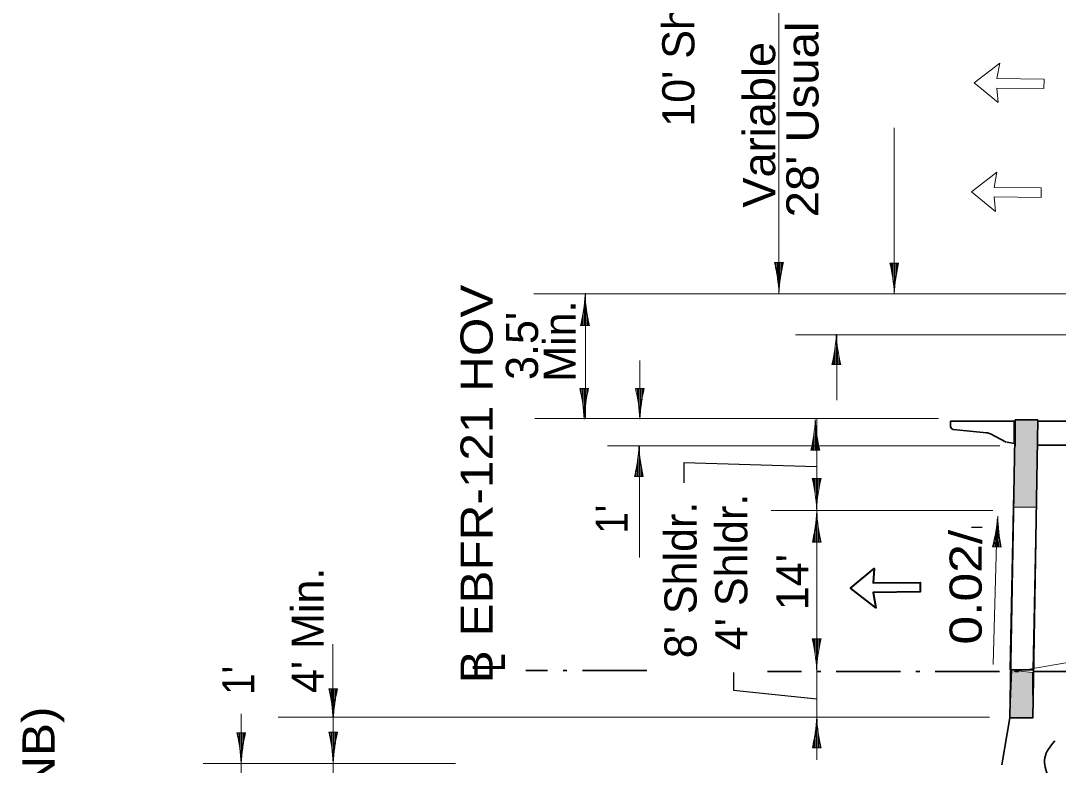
# Model space of a CAD drawing. Extents: x 2363427 to 2368559, y 6957299 to 6980140.
# Drawn here: x 2364021.2 to 2364472.9, y 6965478.2 to 6965802.2 of the extents above; entities that cross this region are included whole.
import ezdxf
from ezdxf.enums import TextEntityAlignment as Align

# ---------------------------------------------------------------- set-up
doc = ezdxf.new("R2010")
doc.units = 0
doc.header["$LTSCALE"] = 5.6
doc.linetypes.add('DOT_DASHED', pattern=[7.7, 5, -1.2, 0.3, -1.2])
for name, color, linetype, lineweight in [('3', 7, 'Continuous', 35), ('4', 7, 'Continuous', 13), ('40', 7, 'Continuous', 35), ('8', 7, 'Continuous', 13)]:
    doc.layers.add(name, color=color, linetype=linetype, lineweight=lineweight)

msp = doc.modelspace()

# ---------------------------------------------------------------- hatches: boundary and pattern name
at = {"layer": '3'}
for points in [[(2364453.307, 6965590.426), (2364463.308, 6965590.426), (2364464.111, 6965628.54), (2364454.108, 6965628.448)], [(2364451.842, 6965498.794), (2364461.842, 6965498.706), (2364461.692, 6965518.588), (2364452.71, 6965519.586)]]:
    msp.add_hatch(color=256, dxfattribs=at).paths.add_polyline_path(points)

# ---------------------------------------------------------------- linework, layer by layer
for p, q in [((2364426.073, 6965627.886), (2364426.073, 6965625.572)), ((2364454.108, 6965628.448), (2364451.842, 6965498.794)), ((2364454.108, 6965628.448), (2364464.111, 6965628.54)), ((2364454.108, 6965628.448), (2364454.108, 6965622.824)), ((2364464.108, 6965628.406), (2364461.842, 6965498.706)), ((2364464.128, 6965627.874), (2364534.151, 6965627.874)), ((2364427.179, 6965624.35), (2364441.663, 6965622.896)), ((2364454.108, 6965617.198), (2364454.108, 6965622.824)), ((2364443.493, 6965622.354), (2364450.328, 6965618.84)), ((2364450.496, 6965618.774), (2364450.506, 6965618.748)), ((2364463.949, 6965617.418), (2364530.245, 6965617.418)), ((2364461.843, 6965519.618), (2364451.842, 6965519.618)), ((2364451.842, 6965498.794), (2364448.359, 6965478.362)), ((2364461.843, 6965498.794), (2364451.842, 6965498.794))]:
    msp.add_line(p, q, dxfattribs=at)
at = {"layer": '3', "lineweight": 13}
msp.add_line((2364576.328, 6965540.2), (2364453.55, 6965518.805), dxfattribs=at)
at = {"layer": '3', "linetype": 'DOT_DASHED'}
msp.add_line((2364293.747, 6965519.428), (2364241.191, 6965519.428), dxfattribs=at)
at = {"layer": '3'}
for points in [[(2364453.793, 6965618.256), (2364453.793, 6965627.886), (2364426.073, 6965627.886)], [(2364450.707, 6965618.718), (2364453.847, 6965618.248), (2364450.506, 6965618.748)]]:
    msp.add_lwpolyline(points, dxfattribs=at)
at = {"layer": '3', "lineweight": 13}
for points in [[(2364453.307, 6965590.426), (2364463.308, 6965590.426), (2364464.111, 6965628.54), (2364454.108, 6965628.448)], [(2364451.842, 6965519.618), (2364461.843, 6965519.618), (2364463.308, 6965590.426), (2364453.307, 6965590.426)], [(2364451.842, 6965498.794), (2364461.842, 6965498.706), (2364461.692, 6965518.588), (2364452.71, 6965519.586)]]:
    msp.add_lwpolyline(points, close=True, dxfattribs=at)
at = {"layer": '3'}
for centre, radius, start, end in [((2364427.303, 6965625.572), 1.229, 180, 264.27822), ((2364441.152, 6965617.803), 5.12, 62.77128, 84.26462)]:
    msp.add_arc(centre, radius, start, end, dxfattribs=at)
msp.add_spline([(2364469.292, 6965454.722), (2364470.404, 6965467.69), (2364468.551, 6965473.248), (2364467.068, 6965481.398), (2364471.517, 6965488.808)], degree=3, dxfattribs=at)
at = {"layer": '4'}
for p, q in [((2364351.339, 6965683.61), (2364351.339, 6965915.843)), ((2364401.539, 6965683.37), (2364401.539, 6965755.631)), ((2364353.253, 6965696.922), (2364349.423, 6965696.922)), ((2364353.253, 6965696.922), (2364349.423, 6965696.922)), ((2364349.903, 6965696.922), (2364349.903, 6965694.54)), ((2364349.903, 6965696.922), (2364349.903, 6965694.54)), ((2364350.403, 6965696.922), (2364350.403, 6965692.06)), ((2364350.403, 6965696.922), (2364350.403, 6965692.06)), ((2364350.903, 6965696.922), (2364350.903, 6965688.312)), ((2364350.903, 6965696.922), (2364350.903, 6965688.312)), ((2364351.403, 6965696.922), (2364351.403, 6965684.358)), ((2364351.403, 6965696.922), (2364351.403, 6965684.358)), ((2364351.903, 6965696.922), (2364351.903, 6965689.572)), ((2364351.903, 6965696.922), (2364351.903, 6965689.572)), ((2364352.403, 6965696.922), (2364352.403, 6965692.645)), ((2364352.403, 6965696.922), (2364352.403, 6965692.645)), ((2364352.903, 6965696.922), (2364352.903, 6965695.336)), ((2364352.903, 6965696.922), (2364352.903, 6965695.336)), ((2364399.625, 6965696.681), (2364403.455, 6965696.681)), ((2364399.625, 6965696.681), (2364403.455, 6965696.681)), ((2364399.975, 6965696.681), (2364399.975, 6965695.097)), ((2364399.975, 6965696.681), (2364399.975, 6965695.097)), ((2364400.475, 6965696.681), (2364400.475, 6965692.405)), ((2364400.475, 6965696.681), (2364400.475, 6965692.405)), ((2364400.975, 6965696.681), (2364400.975, 6965689.331)), ((2364400.975, 6965696.681), (2364400.975, 6965689.331)), ((2364401.475, 6965696.681), (2364401.475, 6965684.117)), ((2364401.475, 6965696.681), (2364401.475, 6965684.117)), ((2364401.975, 6965696.681), (2364401.975, 6965688.072)), ((2364401.975, 6965696.681), (2364401.975, 6965688.072)), ((2364402.475, 6965696.681), (2364402.475, 6965691.819)), ((2364402.475, 6965696.681), (2364402.475, 6965691.819)), ((2364402.975, 6965696.681), (2364402.975, 6965694.3)), ((2364402.975, 6965696.681), (2364402.975, 6965694.3)), ((2364489.927, 6965683.37), (2364244.68, 6965683.37)), ((2364266.973, 6965669.578), (2364266.973, 6965682.142)), ((2364267.09, 6965683.62), (2364267.09, 6965629.024)), ((2364266.473, 6965669.578), (2364266.473, 6965678.188)), ((2364267.473, 6965669.578), (2364267.473, 6965676.928)), ((2364265.973, 6965669.578), (2364265.973, 6965674.44)), ((2364267.973, 6965669.578), (2364267.973, 6965673.854)), ((2364268.823, 6965669.578), (2364264.993, 6965669.578)), ((2364265.473, 6965669.578), (2364265.473, 6965671.96)), ((2364268.473, 6965669.578), (2364268.473, 6965671.162)), ((2364483.333, 6965665.466), (2364358.604, 6965665.466)), ((2364376.368, 6965652.54), (2364376.368, 6965665.104)), ((2364376.485, 6965637.068), (2364376.485, 6965665.46)), ((2364375.868, 6965652.54), (2364375.868, 6965661.15)), ((2364376.868, 6965652.54), (2364376.868, 6965659.89)), ((2364290.781, 6965630.29), (2364290.781, 6965654.358)), ((2364374.868, 6965652.54), (2364374.868, 6965654.922)), ((2364375.368, 6965652.54), (2364375.368, 6965657.402)), ((2364377.368, 6965652.54), (2364377.368, 6965656.816)), ((2364378.218, 6965652.54), (2364374.388, 6965652.54)), ((2364377.868, 6965652.54), (2364377.868, 6965654.124)), ((2364264.624, 6965642.134), (2364268.454, 6965642.134)), ((2364264.974, 6965642.134), (2364264.974, 6965640.55)), ((2364265.474, 6965642.134), (2364265.474, 6965637.858)), ((2364265.974, 6965642.134), (2364265.974, 6965634.784)), ((2364266.474, 6965642.134), (2364266.474, 6965629.57)), ((2364266.974, 6965642.134), (2364266.974, 6965633.524)), ((2364267.474, 6965642.134), (2364267.474, 6965637.272)), ((2364267.974, 6965642.134), (2364267.974, 6965639.752)), ((2364288.866, 6965642.134), (2364292.696, 6965642.134)), ((2364289.216, 6965642.134), (2364289.216, 6965640.55)), ((2364289.716, 6965642.134), (2364289.716, 6965637.858)), ((2364290.216, 6965642.134), (2364290.216, 6965634.784)), ((2364290.716, 6965642.134), (2364290.716, 6965629.57)), ((2364291.216, 6965642.134), (2364291.216, 6965633.524)), ((2364291.716, 6965642.134), (2364291.716, 6965637.272)), ((2364292.216, 6965642.134), (2364292.216, 6965639.752)), ((2364420.867, 6965629.024), (2364244.997, 6965629.024)), ((2364367.228, 6965615.314), (2364367.228, 6965627.878)), ((2364367.787, 6965480.514), (2364367.787, 6965629.024)), ((2364366.728, 6965615.314), (2364366.728, 6965623.924)), ((2364367.728, 6965615.314), (2364367.728, 6965622.664)), ((2364366.228, 6965615.314), (2364366.228, 6965620.176)), ((2364368.228, 6965615.314), (2364368.228, 6965619.592)), ((2364410.25, 6965617.212), (2364276.757, 6965617.212)), ((2364290.439, 6965603.854), (2364290.439, 6965616.418)), ((2364290.556, 6965568.556), (2364290.556, 6965617.298)), ((2364369.078, 6965615.314), (2364365.248, 6965615.314)), ((2364365.728, 6965615.314), (2364365.728, 6965617.696)), ((2364368.728, 6965615.314), (2364368.728, 6965616.9)), ((2364447.535, 6965617.21), (2364406.331, 6965617.21)), ((2364289.939, 6965603.854), (2364289.939, 6965612.462)), ((2364290.939, 6965603.854), (2364290.939, 6965611.204)), ((2364288.939, 6965603.854), (2364288.939, 6965606.234)), ((2364289.439, 6965603.854), (2364289.439, 6965608.716)), ((2364291.439, 6965603.854), (2364291.439, 6965608.13)), ((2364291.939, 6965603.854), (2364291.939, 6965605.438)), ((2364292.289, 6965603.854), (2364288.459, 6965603.854)), ((2364365.825, 6965602.955), (2364369.655, 6965602.955)), ((2364366.175, 6965602.955), (2364366.175, 6965601.37)), ((2364366.675, 6965602.955), (2364366.675, 6965598.678)), ((2364367.175, 6965602.955), (2364367.175, 6965595.605)), ((2364367.675, 6965602.955), (2364367.675, 6965590.391)), ((2364368.175, 6965602.955), (2364368.175, 6965594.346)), ((2364368.675, 6965602.955), (2364368.675, 6965598.093)), ((2364369.175, 6965602.955), (2364369.175, 6965600.574)), ((2364444.476, 6965589.024), (2364347.935, 6965589.024)), ((2364367.863, 6965575.316), (2364367.863, 6965587.88)), ((2364367.363, 6965575.316), (2364367.363, 6965583.926)), ((2364368.363, 6965575.316), (2364368.363, 6965582.666)), ((2364444.616, 6965522.04), (2364446.411, 6965585.324)), ((2364446.269, 6965573.198), (2364446.626, 6965585.758)), ((2364366.363, 6965575.316), (2364366.363, 6965577.698)), ((2364366.863, 6965575.316), (2364366.863, 6965580.178)), ((2364368.863, 6965575.316), (2364368.863, 6965579.592)), ((2364445.27, 6965573.226), (2364445.408, 6965578.086)), ((2364445.77, 6965573.212), (2364446.014, 6965581.818)), ((2364446.769, 6965573.184), (2364446.978, 6965580.53)), ((2364447.269, 6965573.17), (2364447.39, 6965577.444)), ((2364369.713, 6965575.316), (2364365.883, 6965575.316)), ((2364369.363, 6965575.316), (2364369.363, 6965576.9)), ((2364448.119, 6965573.146), (2364444.29, 6965573.254)), ((2364444.77, 6965573.24), (2364444.838, 6965575.622)), ((2364447.769, 6965573.156), (2364447.814, 6965574.74)), ((2364365.825, 6965533.115), (2364369.655, 6965533.115)), ((2364366.175, 6965533.115), (2364366.175, 6965531.53)), ((2364366.675, 6965533.115), (2364366.675, 6965528.838)), ((2364367.175, 6965533.115), (2364367.175, 6965525.765)), ((2364367.675, 6965533.115), (2364367.675, 6965520.551)), ((2364368.175, 6965533.115), (2364368.175, 6965524.506)), ((2364368.675, 6965533.115), (2364368.675, 6965528.253)), ((2364369.175, 6965533.115), (2364369.175, 6965530.734)), ((2364157.557, 6965318.422), (2364157.185, 6965530.886)), ((2364155.361, 6965511.37), (2364159.191, 6965511.37)), ((2364155.711, 6965511.37), (2364155.711, 6965509.785)), ((2364156.211, 6965511.37), (2364156.211, 6965507.094)), ((2364156.711, 6965511.37), (2364156.711, 6965504.02)), ((2364157.211, 6965511.37), (2364157.211, 6965498.806)), ((2364157.711, 6965511.37), (2364157.711, 6965502.76)), ((2364158.211, 6965511.37), (2364158.211, 6965506.508)), ((2364158.711, 6965511.37), (2364158.711, 6965508.988)), ((2364117.231, 6965398.082), (2364117.231, 6965500.496)), ((2364442.968, 6965499.024), (2364133.351, 6965499.024)), ((2364367.863, 6965485.794), (2364367.863, 6965498.358)), ((2364115.316, 6965492.273), (2364119.146, 6965492.273)), ((2364115.666, 6965492.273), (2364115.666, 6965490.688)), ((2364116.166, 6965492.273), (2364116.166, 6965487.996)), ((2364116.666, 6965492.273), (2364116.666, 6965484.923)), ((2364117.166, 6965492.273), (2364117.166, 6965479.709)), ((2364117.666, 6965492.273), (2364117.666, 6965483.664)), ((2364118.166, 6965492.273), (2364118.166, 6965487.411)), ((2364118.666, 6965492.273), (2364118.666, 6965489.892)), ((2364155.361, 6965492.51), (2364159.191, 6965492.51)), ((2364155.711, 6965492.51), (2364155.711, 6965490.924)), ((2364156.211, 6965492.51), (2364156.211, 6965488.233)), ((2364156.711, 6965492.51), (2364156.711, 6965485.16)), ((2364157.211, 6965492.51), (2364157.211, 6965479.946)), ((2364157.711, 6965492.51), (2364157.711, 6965483.9)), ((2364158.211, 6965492.51), (2364158.211, 6965487.648)), ((2364158.711, 6965492.51), (2364158.711, 6965490.128)), ((2364367.363, 6965485.794), (2364367.363, 6965494.404)), ((2364368.363, 6965485.794), (2364368.363, 6965493.144)), ((2364366.363, 6965485.794), (2364366.363, 6965488.176)), ((2364366.863, 6965485.794), (2364366.863, 6965490.656)), ((2364368.863, 6965485.794), (2364368.863, 6965490.07)), ((2364369.363, 6965485.794), (2364369.363, 6965487.378)), ((2364369.713, 6965485.794), (2364365.883, 6965485.794)), ((2364210.47, 6965478.962), (2364100.676, 6965478.962))]:
    msp.add_line(p, q, dxfattribs=at)
at = {"layer": '4', "lineweight": 25}
for p, q in [((2364309.943, 6965609.97), (2364309.943, 6965601.08)), ((2364309.943, 6965609.97), (2364367.723, 6965608.132)), ((2364430.478, 6965578.607), (2364426.302, 6965578.607)), ((2364435.119, 6965581.853), (2364439.759, 6965581.853))]:
    msp.add_line(p, q, dxfattribs=at)
at = {"layer": '4', "linetype": 'DOT_DASHED', "lineweight": 35}
msp.add_line((2364490.476, 6965519.024), (2364346.309, 6965519.024), dxfattribs=at)
at = {"layer": '4', "lineweight": 25}
msp.add_lwpolyline([(2364331.553, 6965518.476), (2364331.553, 6965510.856), (2364367.765, 6965507.046)], dxfattribs=at)
at = {"layer": '4'}
for centre, start, end in [((2364279.214, 6965680.028), 2.84356, 13.52961), ((2364279.214, 6965680.028), 2.84356, 13.52961), ((2364423.461, 6965680.028), 166.47039, 177.15644), ((2364423.461, 6965680.028), 166.47039, 177.15644), ((2364329.415, 6965679.787), 2.84356, 13.52961), ((2364329.415, 6965679.787), 2.84356, 13.52961), ((2364473.662, 6965679.787), 166.47039, 177.15644), ((2364473.662, 6965679.787), 166.47039, 177.15644), ((2364194.785, 6965686.472), 346.47039, 357.15644), ((2364339.032, 6965686.472), 182.84356, 193.52961), ((2364304.18, 6965669.434), 346.47039, 357.15644), ((2364448.427, 6965669.434), 182.84356, 193.52961), ((2364194.417, 6965625.241), 2.84356, 13.52961), ((2364338.664, 6965625.241), 166.47039, 177.15644), ((2364218.658, 6965625.241), 2.84356, 13.52961), ((2364362.905, 6965625.241), 166.47039, 177.15644), ((2364295.039, 6965632.21), 346.47039, 357.15644), ((2364439.286, 6965632.21), 182.84356, 193.52961), ((2364218.251, 6965620.748), 346.47039, 357.15644), ((2364362.498, 6965620.748), 182.84356, 193.52961), ((2364295.617, 6965586.062), 2.84356, 13.52961), ((2364439.864, 6965586.062), 166.47039, 177.15644), ((2364295.675, 6965592.21), 346.47039, 357.15644), ((2364439.922, 6965592.21), 182.84356, 193.52961), ((2364374.59, 6965592.132), 344.84626, 355.53231), ((2364518.779, 6965588.044), 181.21943, 191.90548), ((2364295.617, 6965516.222), 2.84356, 13.52961), ((2364439.864, 6965516.222), 166.47039, 177.15644), ((2364085.153, 6965494.477), 2.84356, 13.52961), ((2364229.4, 6965494.477), 166.47039, 177.15644), ((2364295.675, 6965502.689), 346.47039, 357.15644), ((2364439.922, 6965502.689), 182.84356, 193.52961), ((2364045.108, 6965475.38), 2.84356, 13.52961), ((2364189.355, 6965475.38), 166.47039, 177.15644), ((2364085.153, 6965475.616), 2.84356, 13.52961), ((2364229.4, 6965475.616), 166.47039, 177.15644)]:
    msp.add_arc(centre, 72.212, start, end, dxfattribs=at)
at = {"layer": '40', "lineweight": 13}
for p, q in [((2364446.197, 6965772.905), (2364466.703, 6965772.71)), ((2364445.012, 6965725.512), (2364465.517, 6965725.317))]:
    msp.add_line(p, q, dxfattribs=at)
at = {"layer": '40'}
msp.add_line((2364392.313, 6965557.51), (2364412.818, 6965557.706), dxfattribs=at)
at = {"layer": '40', "lineweight": 13}
for points in [[(2364446.197, 6965772.905), (2364446.73, 6965766.59), (2364436.343, 6965775.125), (2364447.443, 6965783.727), (2364446.235, 6965777)], [(2364446.235, 6965777), (2364466.74, 6965776.805), (2364466.703, 6965772.71)], [(2364445.012, 6965725.512), (2364445.545, 6965719.197), (2364435.157, 6965727.732), (2364446.257, 6965736.335), (2364445.049, 6965729.607)], [(2364445.049, 6965729.607), (2364465.555, 6965729.412), (2364465.517, 6965725.317)]]:
    msp.add_lwpolyline(points, dxfattribs=at)
at = {"layer": '40'}
for points in [[(2364392.313, 6965557.51), (2364392.845, 6965563.826), (2364382.458, 6965555.29), (2364393.558, 6965546.688), (2364392.35, 6965553.416)], [(2364392.35, 6965553.416), (2364412.855, 6965553.61), (2364412.818, 6965557.706)]]:
    msp.add_lwpolyline(points, dxfattribs=at)
at = {"layer": '8'}
for points in [[(2364436.343, 6965775.125), (2364446.73, 6965766.59), (2364446.197, 6965772.905), (2364466.703, 6965772.71), (2364466.74, 6965776.805), (2364446.235, 6965777), (2364447.443, 6965783.727)], [(2364435.157, 6965727.732), (2364445.545, 6965719.197), (2364445.012, 6965725.512), (2364465.517, 6965725.317), (2364465.555, 6965729.412), (2364445.049, 6965729.607), (2364446.257, 6965736.335)]]:
    msp.add_lwpolyline(points, close=True, dxfattribs=at)
at = {"layer": '8', "lineweight": 40}
msp.add_lwpolyline([(2364382.458, 6965555.29), (2364392.845, 6965563.826), (2364392.313, 6965557.51), (2364412.818, 6965557.706), (2364412.855, 6965553.61), (2364392.35, 6965553.416), (2364393.558, 6965546.688)], close=True, dxfattribs=at)

# ---------------------------------------------------------------- texts
at = {"layer": '4'}
for s, p in [("10' Shldr.", (2364314.526, 6965795.323)), ('Min. ', (2364262.837, 6965665.345)), ("3.5' ", (2364246.455, 6965663.279)), ("8' Shldr.", (2364315.49, 6965558.82)), ("4' Shldr.", (2364337.587, 6965562.276)), ("14'", (2364364.135, 6965557.881)), ("4' Min.", (2364153.121, 6965536.863))]:
    msp.add_text(s, height=14, rotation=90, dxfattribs=at).set_placement(p, align=Align.CENTER)
for s, width, p in [("28' Usual", 1.1, (2364368.541, 6965759.231)), ('Variable', 1.05, (2364349.7, 6965756.925)), ('B EBFR-121 HOV', 1.15, (2364226.705, 6965600.582)), ("1' ", 0.9, (2364285.536, 6965587.541)), ('0.02/', 1.2, (2364439.617, 6965555.664)), ('L', 0.75, (2364232.033, 6965522.795)), ("1' ", 0.9, (2364122.989, 6965517.439)), ('121 HOV (NB)', 1.15, (2364035.989, 6965434.327))]:
    msp.add_text(s, height=14, rotation=90, dxfattribs=dict(at, width=width)).set_placement(p, align=Align.CENTER)

doc.saveas('drawing.dxf')
